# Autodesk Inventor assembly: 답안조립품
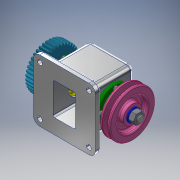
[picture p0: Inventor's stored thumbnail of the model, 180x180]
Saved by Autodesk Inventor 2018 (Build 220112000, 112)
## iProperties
Created: 2022-07
Part Number: 답안조립품
Material: 일반
Document SubType Name: Assembly
Designer: home
Author: home
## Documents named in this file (12)
- C:\Users\kimgi\Desktop\720706V1014\답안조립품.iam
- C:\Users\kimgi\Desktop\720706V1014\본체.ipt
- C:\Users\kimgi\Desktop\720706V1014\커버.ipt
- C:\Users\kimgi\Desktop\720706V1014\베어링 6204.ipt
- C:\Users\kimgi\Desktop\720706V1014\오일실 20x35x8.ipt
- C:\Users\kimgi\Desktop\720706V1014\축.ipt
- C:\Users\kimgi\Desktop\720706V1014\키 5x5.ipt
- C:\Users\kimgi\Desktop\720706V1014\V벨트풀리.ipt
- C:\Users\kimgi\Desktop\720706V1014\스퍼기어.ipt
- C:\Users\kimgi\Desktop\720706V1014\와셔 12x24.ipt
- C:\Users\kimgi\Desktop\720706V1014\너트 M12x1.25.ipt
- C:\Users\kimgi\Desktop\720706V1014\볼트 M4x0.7.ipt
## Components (1 placed, 1 different names)
1. V벨트풀리:2
